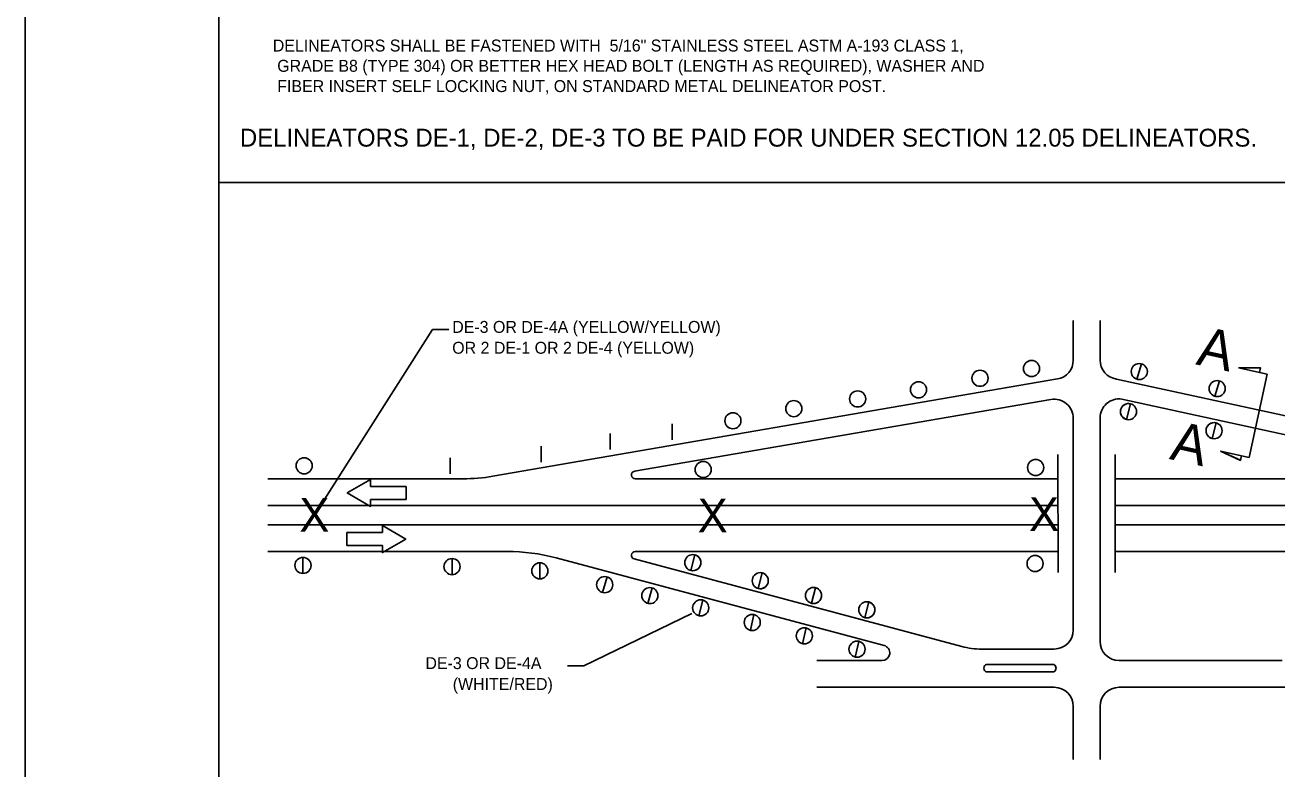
# Model space of a CAD drawing. Extents: x -0.14 to 2.7, y -0.05 to 1.78.
# Drawn here: x -0.135 to 0.739, y 0.749 to 1.269 of the extents above; entities that cross this region are included whole.
import ezdxf

# ---------------------------------------------------------------- set-up
doc = ezdxf.new("R2010")
doc.units = 0
for name, color, linetype in [('BDR_Outer_Perimeter', 7, 'Continuous'), ('BDR_Perimeter', 7, 'Continuous'), ('CT_CSHT_GeneralLabel', 7, 'Continuous')]:
    doc.layers.add(name, color=color, linetype=linetype)

msp = doc.modelspace()

# ---------------------------------------------------------------- linework, layer by layer
at = {"layer": 'BDR_Outer_Perimeter'}
msp.add_lwpolyline([(-0.13539, -0.05208), (2.69793, -0.05208), (2.69793, 1.78125), (-0.13539, 1.78125)], close=True, dxfattribs=at)
at = {"layer": 'BDR_Perimeter'}
msp.add_line((0, 1.72917), (0, 0), dxfattribs=at)
at = {"layer": 'CT_CSHT_GeneralLabel'}
for p, q in [((2.64583, 1.15912), (0, 1.15912)), ((0.59693, 1.035), (0.59693, 1.06274)), ((0.61562, 1.03501), (0.61562, 1.06274)), ((0.14931, 1.0564), (0.07245, 0.93565)), ((0.1606, 1.0564), (0.14931, 1.0564)), ((0.64468, 1.03241), (0.64141, 1.02163)), ((0.73248, 1.02519), (0.71243, 1.02957)), ((0.71243, 1.02957), (0.72777, 1.02954)), ((0.71977, 0.96694), (0.73248, 1.02519)), ((0.72708, 1.02642), (0.72777, 1.02954)), ((0.58584, 1.02184), (0.19144, 0.9539)), ((0.62718, 1.02177), (0.85708, 0.9716)), ((0.69906, 1.02053), (0.69584, 1.00973)), ((0.5813, 1.00751), (0.2905, 0.95741)), ((0.63077, 1.00781), (0.88602, 0.95211)), ((0.63412, 0.99359), (0.63696, 1.00449)), ((0.31671, 0.97934), (0.31671, 0.9906)), ((0.59693, 0.84654), (0.59693, 0.99435)), ((0.61562, 0.83852), (0.61562, 0.99458)), ((0.69386, 0.98027), (0.6967, 0.99117)), ((0.27335, 0.97255), (0.27335, 0.98381)), ((0.22508, 0.96364), (0.22508, 0.9749)), ((0.71977, 0.96694), (0.69972, 0.97132)), ((0.69972, 0.97132), (0.71369, 0.96501)), ((0.16167, 0.95557), (0.16166, 0.96684)), ((0.58625, 0.88659), (0.58624, 0.9692)), ((0.6263, 0.88659), (0.6263, 0.9692)), ((0.71369, 0.96501), (0.71437, 0.96812)), ((0.03415, 0.95211), (0.17058, 0.95211)), ((0.10603, 0.94678), (0.13087, 0.94678)), ((0.13087, 0.93757), (0.13087, 0.94678)), ((0.58624, 0.95211), (0.29096, 0.95211)), ((0.6263, 0.95211), (0.88602, 0.95211)), ((0.10605, 0.93757), (0.13087, 0.93757)), ((0.03415, 0.93341), (0.58625, 0.93341)), ((0.6263, 0.93341), (1.18009, 0.93341)), ((0.03415, 0.92006), (0.58624, 0.92006)), ((0.6263, 0.92006), (1.31714, 0.92006)), ((0.08939, 0.91468), (0.0894, 0.90547)), ((0.11422, 0.91468), (0.08939, 0.91468)), ((0.03415, 0.90136), (0.20127, 0.90136)), ((0.11423, 0.90547), (0.0894, 0.90547)), ((0.58624, 0.90136), (0.2909, 0.90136)), ((0.6263, 0.90136), (0.86882, 0.90136)), ((0.05878, 0.89722), (0.05878, 0.88596)), ((0.1629, 0.88513), (0.16291, 0.89639)), ((0.22426, 0.88216), (0.22426, 0.89342)), ((0.46474, 0.83567), (0.23573, 0.89683)), ((0.51904, 0.83498), (0.2902, 0.89612)), ((0.33256, 0.89897), (0.32971, 0.88806)), ((0.26793, 0.87276), (0.27122, 0.88354)), ((0.37966, 0.88638), (0.37682, 0.87547)), ((0.30263, 0.87594), (0.29961, 0.86508)), ((0.41688, 0.87603), (0.41403, 0.86513)), ((0.33804, 0.86739), (0.33524, 0.85648)), ((0.45409, 0.86606), (0.45125, 0.85516)), ((0.25493, 0.82152), (0.33037, 0.85809)), ((0.37386, 0.85725), (0.37142, 0.84625)), ((0.41026, 0.84792), (0.40783, 0.83691)), ((0.4472, 0.83855), (0.44452, 0.82761)), ((0.53283, 0.83317), (0.58356, 0.83317)), ((0.41785, 0.82517), (0.46336, 0.82517)), ((0.58356, 0.82249), (0.53632, 0.82249)), ((0.62898, 0.82517), (0.74294, 0.82517)), ((0.24363, 0.82152), (0.25493, 0.82152)), ((0.58356, 0.81716), (0.53632, 0.81716)), ((0.41785, 0.80647), (0.58357, 0.80647)), ((0.62898, 0.80647), (0.80331, 0.80647)), ((0.59693, 0.75591), (0.59693, 0.79312)), ((0.61562, 0.75592), (0.61562, 0.79312))]:
    msp.add_line(p, q, dxfattribs=at)
for points in [[(0.71243, 1.02957), (0.72777, 1.02954), (0.72708, 1.02642)], [(0.69972, 0.97132), (0.71367, 0.96495), (0.71435, 0.96808)]]:
    msp.add_lwpolyline(points, close=True, dxfattribs=at)
for points in [[(0.10604, 0.94678), (0.10604, 0.95169), (0.08968, 0.94225), (0.10604, 0.9328), (0.10605, 0.93757)], [(0.11422, 0.90547), (0.11422, 0.90056), (0.13059, 0.91), (0.11422, 0.91944), (0.11422, 0.91468)]]:
    msp.add_lwpolyline(points, dxfattribs=at)
for centre in [(0.56777, 1.02914), (0.64304, 1.02702), (0.53177, 1.02235), (0.48882, 1.01429), (0.69745, 1.01513), (0.40168, 1.00113), (0.44627, 1.00792), (0.35914, 0.99265), (0.63554, 0.99904), (0.69528, 0.98572), (0.0596, 0.96119), (0.33838, 0.95857), (0.57063, 0.95996), (0.05878, 0.89159), (0.16291, 0.89075), (0.22426, 0.88779), (0.33113, 0.89352), (0.57023, 0.89291), (0.26957, 0.87815), (0.37824, 0.88092), (0.30112, 0.87051), (0.41545, 0.87058), (0.33664, 0.86194), (0.45267, 0.86061), (0.37264, 0.85175), (0.40905, 0.84242), (0.44586, 0.83308)]:
    msp.add_circle(centre, 0.00563, dxfattribs=at)
for centre, radius, start, end in [((0.58357, 1.035), 0.01335, 279.77351, 359.99999), ((0.62897, 1.03501), 0.01335, 180, 262.25989), ((0.58357, 0.99435), 0.01335, 360, 99.76689), ((0.62897, 0.99458), 0.01335, 82.2625, 180), ((0.63554, 0.99904), 0.00563, 75.38473, 255.38473), ((0.69528, 0.98572), 0.00563, 75.38473, 255.38473), ((0.17058, 1.07496), 0.12286, 270, 279.77642), ((0.29096, 0.95478), 0.00267, 99.77782, 270), ((0.20127, 0.76782), 0.13354, 75.04524, 90), ((0.2909, 0.89869), 0.00267, 90, 255.04621), ((0.33113, 0.89352), 0.00563, 255.38473, 75.38473), ((0.37824, 0.88092), 0.00563, 255.38473, 75.38473), ((0.41545, 0.87058), 0.00563, 255.38473, 75.38473), ((0.45267, 0.86061), 0.00563, 255.38473, 75.38473), ((0.58357, 0.84653), 0.01335, 270, 360), ((0.46336, 0.83051), 0.00534, 270, 75.04323), ((0.53282, 0.88659), 0.05342, 255.04124, 270), ((0.62897, 0.83852), 0.01335, 180, 270), ((0.53729, 0.81982), 0.00284, 109.98961, 250.01038), ((0.58166, 0.81982), 0.00328, 305.56022, 54.43978), ((0.58357, 0.79311), 0.01335, 360, 90), ((0.62897, 0.79311), 0.01335, 90, 179.99999)]:
    msp.add_arc(centre, radius, start, end, dxfattribs=at)

# ---------------------------------------------------------------- texts
for s, height, p in [('DELINEATORS SHALL BE FASTENED WITH  5/16" STAINLESS STEEL ASTM A-193 CLASS 1,', 0.0083333, (0.03769, 1.25061)), (' GRADE B8 (TYPE 304) OR BETTER HEX HEAD BOLT (LENGTH AS REQUIRED), WASHER AND', 0.0083333, (0.03769, 1.23644)), (' FIBER INSERT SELF LOCKING NUT, ON STANDARD METAL DELINEATOR POST.', 0.0083333, (0.03769, 1.22227)), ('DELINEATORS DE-1, DE-2, DE-3 TO BE PAID FOR UNDER SECTION 12.05 DELINEATORS.', 0.0125, (0.01473, 1.18417)), ('DE-3 OR DE-4A (YELLOW/YELLOW)', 0.0083333, (0.16303, 1.05405)), ('OR 2 DE-1 OR 2 DE-4 (YELLOW)', 0.0083333, (0.16303, 1.03947)), ('X', 0.02351, (0.05626, 0.91518)), ('X', 0.02351, (0.33454, 0.91474)), ('X', 0.02351, (0.56601, 0.91575)), ('DE-3 OR DE-4A', 0.0083333, (0.14429, 0.81917)), ('(WHITE/RED)', 0.0083333, (0.1634, 0.80459))]:
    msp.add_text(s, height=height, dxfattribs=at).set_placement(p)
for p in [(0.68201, 1.03212), (0.66355, 0.96599)]:
    msp.add_text('A', height=0.02742, rotation=347.69011, dxfattribs=at).set_placement(p)

doc.saveas('drawing.dxf')
